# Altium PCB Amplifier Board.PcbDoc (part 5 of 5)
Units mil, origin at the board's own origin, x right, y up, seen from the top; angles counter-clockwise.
Board outline 6000 x 4000 mil, 6 copper layers (Top Layer, GND, VCC, InternalPlane3, InternalPlane4, Bottom Layer); 880 components, 519 nets, 2020 pads, 372 vias.
Unrouted connection lines stored in the file: 585.
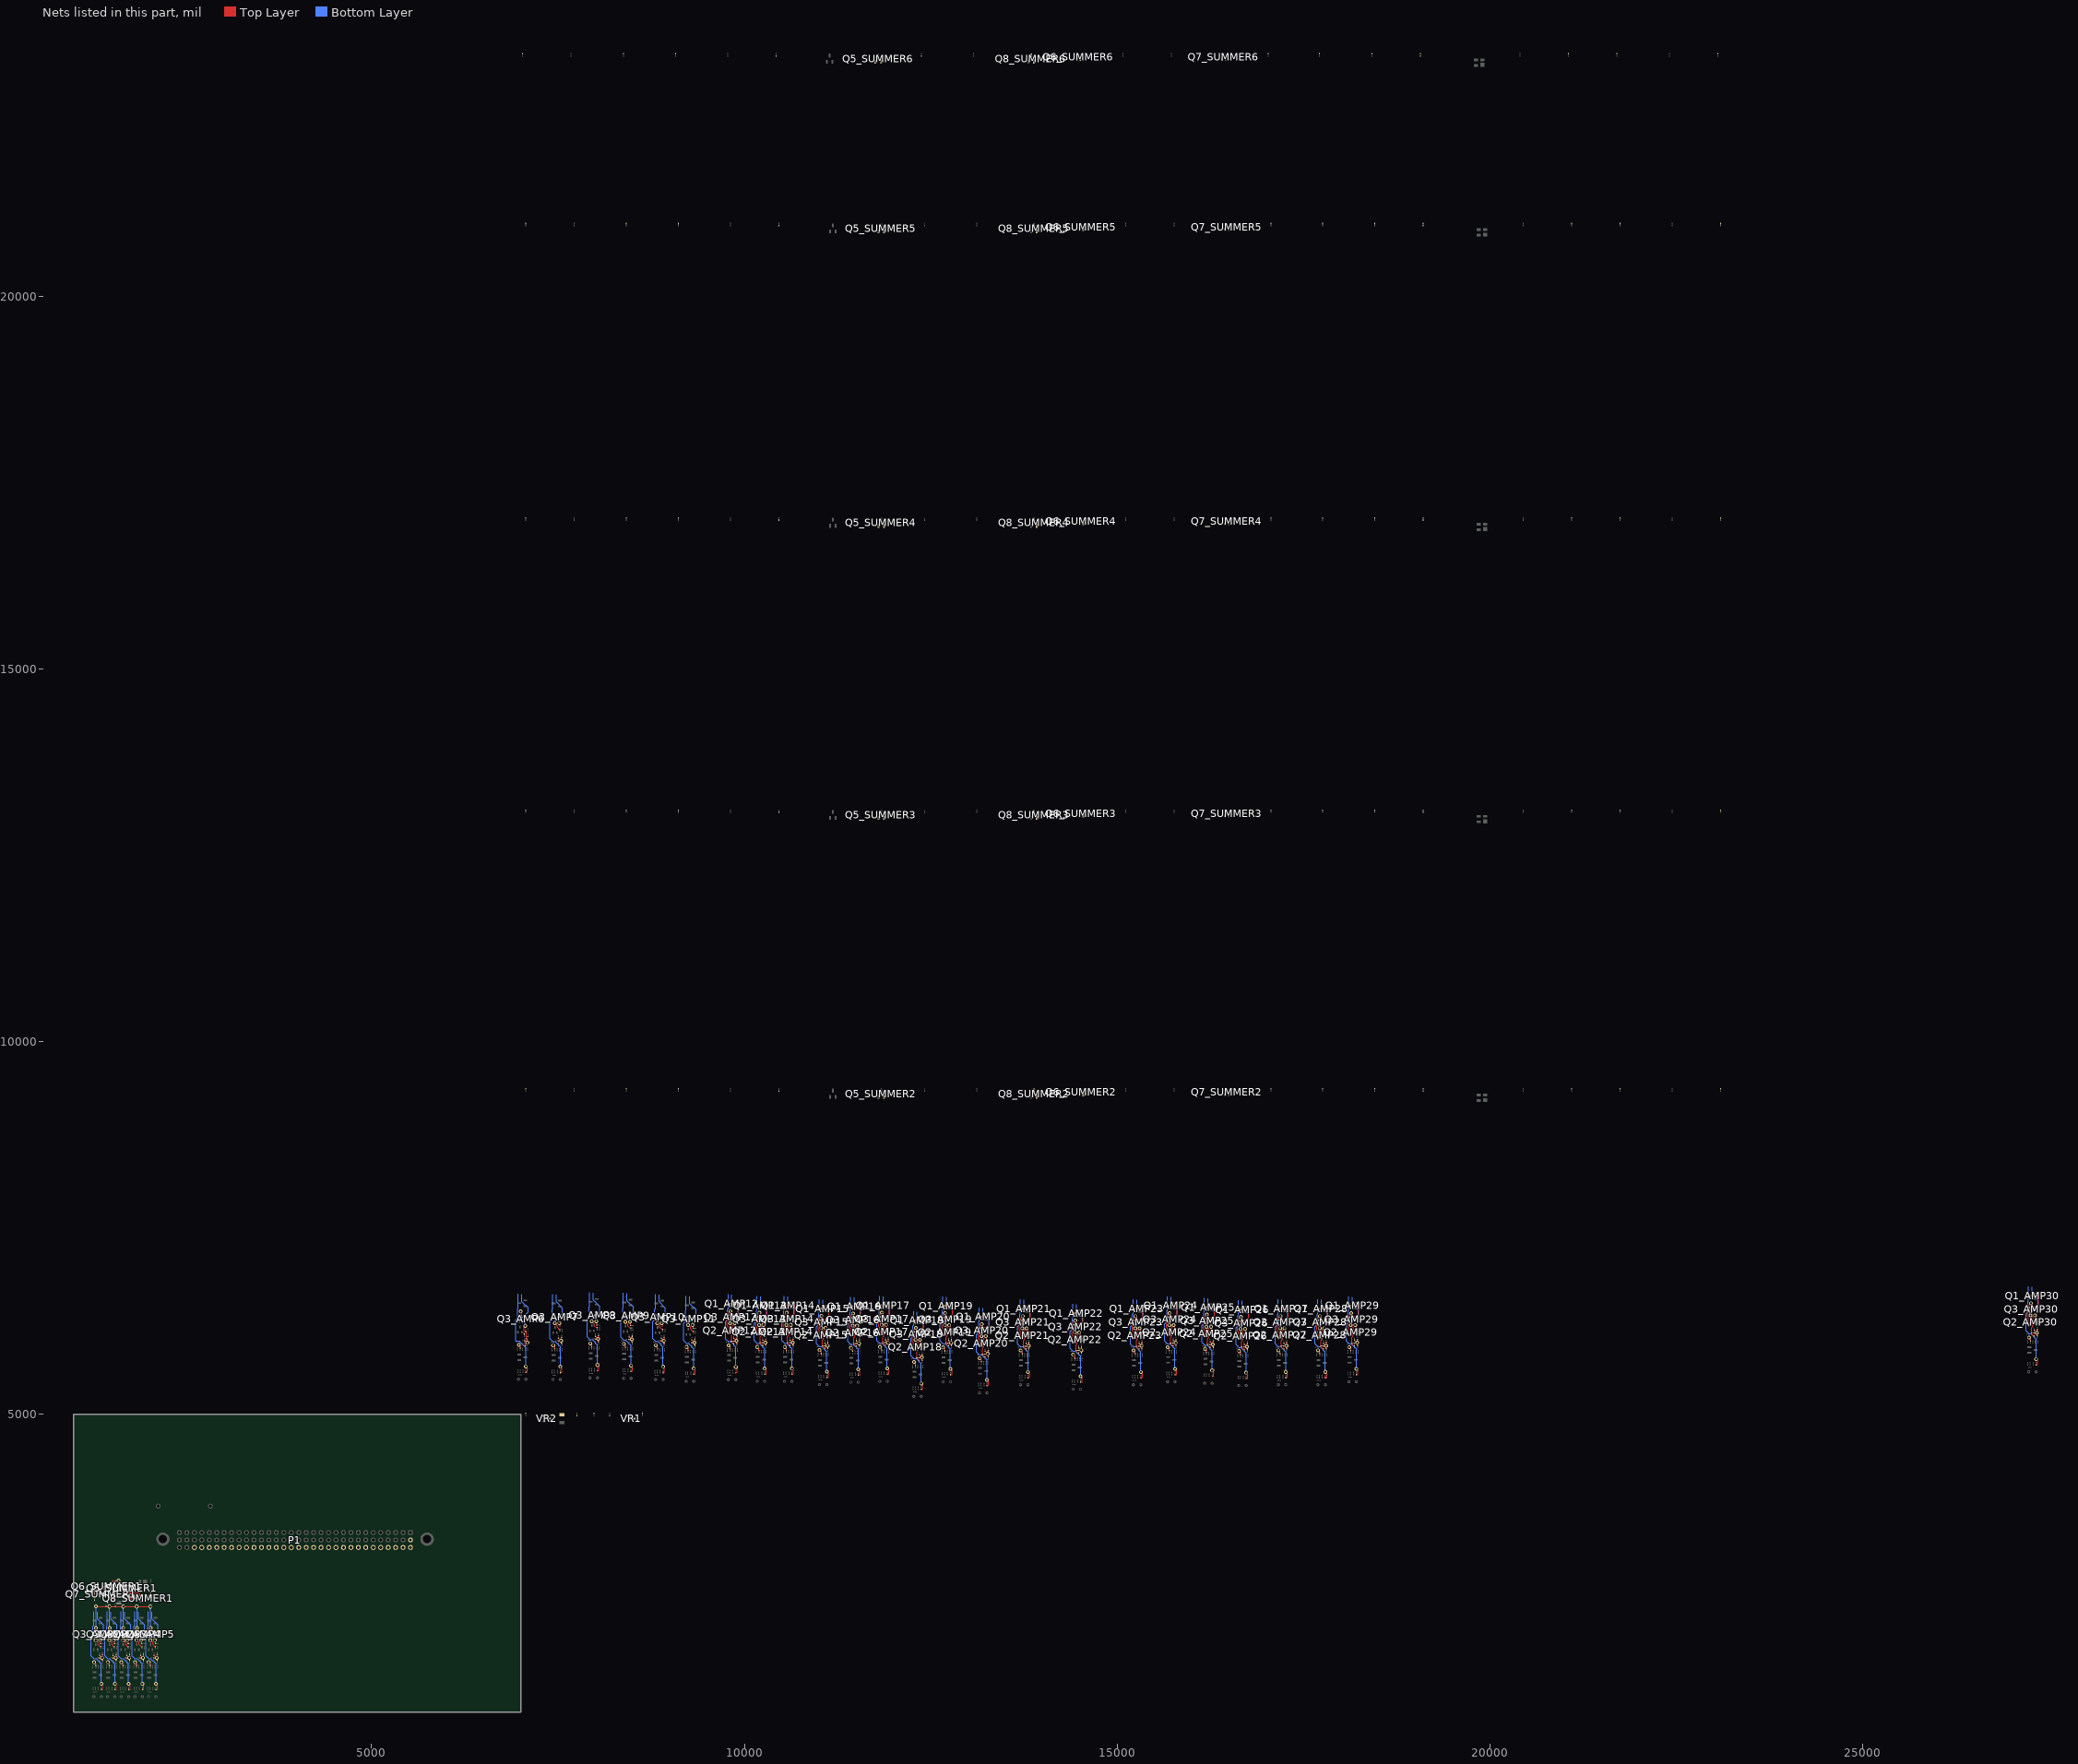
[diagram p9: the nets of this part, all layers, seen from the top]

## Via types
v1: diameter 50, hole 28, Top Layer to Bottom Layer, 371 vias
v2: diameter 50, hole 28, Top Layer to Bottom Layer, tented top, 1 vias

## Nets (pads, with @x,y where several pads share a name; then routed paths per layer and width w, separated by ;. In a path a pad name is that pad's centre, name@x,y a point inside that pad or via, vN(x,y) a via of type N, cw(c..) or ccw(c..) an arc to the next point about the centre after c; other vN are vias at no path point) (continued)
NetQ1_AMP12_3: Q1_AMP12.3 Q2_AMP12.1 Q3_AMP12.1 R2_AMP12.2 R4_AMP12.1 | length 902.3
  Top Layer w7: Q3_AMP12.1@9786.57,6326.59 9786.57,6355.57 v1(9814,6383) v1@9824.57,6372.43 ; Q1_AMP12.3@9793.66,6482 9916,6482 9916,6364 9895,6343 9844,6343 9824,6323 9824,6309 9790.41,6275.41 9786.57,6275.41 9770,6258.84 9770,6194.2 9781.1,6183.1 9781,6183.1 9781,6129 9784,6126 9812,6126 9837.59,6100.41 9837.59,6069.59 9826.22,6058.22 9826.22,5970.78 9851.22,5945.78 R2_AMP12.2@9860,5945.78
NetQ1_AMP13_3: Q1_AMP13.3 Q2_AMP13.1 Q3_AMP13.1 R2_AMP13.2 R4_AMP13.1 | length 902.3
  Top Layer w7: Q3_AMP13.1@10173.57,6304.59 10173.57,6333.57 v1(10201,6361) v1@10211.57,6350.43 ; Q1_AMP13.3@10180.66,6460 10303,6460 10303,6342 10282,6321 10231,6321 10211,6301 10211,6287 10177.41,6253.41 10173.57,6253.41 10157,6236.84 10157,6172.2 10168.1,6161.1 10168,6161.1 10168,6107 10171,6104 10199,6104 10224.59,6078.41 10224.59,6047.59 10213.22,6036.22 10213.22,5948.78 10238.22,5923.78 R2_AMP13.2@10247,5923.78
NetQ1_AMP14_3: Q1_AMP14.3 Q2_AMP14.1 Q3_AMP14.1 R2_AMP14.2 R4_AMP14.1 | length 902.3
  Top Layer w7: Q3_AMP14.1@10539.57,6304.59 10539.57,6333.57 v1(10567,6361) v1@10577.57,6350.43 ; Q1_AMP14.3@10546.66,6460 10669,6460 10669,6342 10648,6321 10597,6321 10577,6301 10577,6287 10543.41,6253.41 10539.57,6253.41 10523,6236.84 10523,6172.2 10534.1,6161.1 10534,6161.1 10534,6107 10537,6104 10565,6104 10590.59,6078.41 10590.59,6047.59 10579.22,6036.22 10579.22,5948.78 10604.22,5923.78 R2_AMP14.2@10613,5923.78
NetQ1_AMP15_3: Q1_AMP15.3 Q2_AMP15.1 Q3_AMP15.1 R2_AMP15.2 R4_AMP15.1 | length 902.3
  Top Layer w7: Q3_AMP15.1@11007.57,6261.59 11007.57,6290.57 v1(11035,6318) v1@11045.57,6307.43 ; Q1_AMP15.3@11014.66,6417 11137,6417 11137,6299 11116,6278 11065,6278 11045,6258 11045,6244 11011.41,6210.41 11007.57,6210.41 10991,6193.84 10991,6129.2 11002.1,6118.1 11002,6118.1 11002,6064 11005,6061 11033,6061 11058.59,6035.41 11058.59,6004.59 11047.22,5993.22 11047.22,5905.78 11072.22,5880.78 R2_AMP15.2@11081,5880.78
NetQ1_AMP16_3: Q1_AMP16.3 Q2_AMP16.1 Q3_AMP16.1 R2_AMP16.2 R4_AMP16.1 | length 902.3
  Top Layer w7: Q3_AMP16.1@11429.57,6293.59 11429.57,6322.57 v1(11457,6350) v1@11467.57,6339.43 ; Q1_AMP16.3@11436.66,6449 11559,6449 11559,6331 11538,6310 11487,6310 11467,6290 11467,6276 11433.41,6242.41 11429.57,6242.41 11413,6225.84 11413,6161.2 11424.1,6150.1 11424,6150.1 11424,6096 11427,6093 11455,6093 11480.59,6067.41 11480.59,6036.59 11469.22,6025.22 11469.22,5937.78 11494.22,5912.78 R2_AMP16.2@11503,5912.78
NetQ1_AMP17_3: Q1_AMP17.3 Q2_AMP17.1 Q3_AMP17.1 R2_AMP17.2 R4_AMP17.1 | length 902.3
  Top Layer w7: Q3_AMP17.1@11817.57,6305.59 11817.57,6334.57 v1(11845,6362) v1@11855.57,6351.43 ; Q1_AMP17.3@11824.66,6461 11947,6461 11947,6343 11926,6322 11875,6322 11855,6302 11855,6288 11821.41,6254.41 11817.57,6254.41 11801,6237.84 11801,6173.2 11812.1,6162.1 11812,6162.1 11812,6108 11815,6105 11843,6105 11868.59,6079.41 11868.59,6048.59 11857.22,6037.22 11857.22,5949.78 11882.22,5924.78 R2_AMP17.2@11891,5924.78
NetQ1_AMP18_3: Q1_AMP18.3 Q2_AMP18.1 Q3_AMP18.1 R2_AMP18.2 R4_AMP18.1 | length 902.3
  Top Layer w7: Q3_AMP18.1@12273.57,6103.59 12273.57,6132.57 v1(12301,6160) v1@12311.57,6149.43 ; Q1_AMP18.3@12280.66,6259 12403,6259 12403,6141 12382,6120 12331,6120 12311,6100 12311,6086 12277.41,6052.41 12273.57,6052.41 12257,6035.84 12257,5971.2 12268.1,5960.1 12268,5960.1 12268,5906 12271,5903 12299,5903 12324.59,5877.41 12324.59,5846.59 12313.22,5835.22 12313.22,5747.78 12338.22,5722.78 R2_AMP18.2@12347,5722.78
NetQ1_AMP19_3: Q1_AMP19.3 Q2_AMP19.1 Q3_AMP19.1 R2_AMP19.2 R4_AMP19.1 | length 902.3
  Top Layer w7: Q3_AMP19.1@12665.57,6299.59 12665.57,6328.57 v1(12693,6356) v1@12703.57,6345.43 ; Q1_AMP19.3@12672.66,6455 12795,6455 12795,6337 12774,6316 12723,6316 12703,6296 12703,6282 12669.41,6248.41 12665.57,6248.41 12649,6231.84 12649,6167.2 12660.1,6156.1 12660,6156.1 12660,6102 12663,6099 12691,6099 12716.59,6073.41 12716.59,6042.59 12705.22,6031.22 12705.22,5943.78 12730.22,5918.78 R2_AMP19.2@12739,5918.78
NetQ1_AMP20_3: Q1_AMP20.3 Q2_AMP20.1 Q3_AMP20.1 R2_AMP20.2 R4_AMP20.1 | length 902.3
  Top Layer w7: Q3_AMP20.1@13155.57,6152.59 13155.57,6181.57 v1(13183,6209) v1@13193.57,6198.43 ; Q1_AMP20.3@13162.66,6308 13285,6308 13285,6190 13264,6169 13213,6169 13193,6149 13193,6135 13159.41,6101.41 13155.57,6101.41 13139,6084.84 13139,6020.2 13150.1,6009.1 13150,6009.1 13150,5955 13153,5952 13181,5952 13206.59,5926.41 13206.59,5895.59 13195.22,5884.22 13195.22,5796.78 13220.22,5771.78 R2_AMP20.2@13229,5771.78
NetQ1_AMP21_3: Q1_AMP21.3 Q2_AMP21.1 Q3_AMP21.1 R2_AMP21.2 R4_AMP21.1 | length 902.3
  Top Layer w7: Q3_AMP21.1@13705.57,6258.59 13705.57,6287.57 v1(13733,6315) v1@13743.57,6304.43 ; Q1_AMP21.3@13712.66,6414 13835,6414 13835,6296 13814,6275 13763,6275 13743,6255 13743,6241 13709.41,6207.41 13705.57,6207.41 13689,6190.84 13689,6126.2 13700.1,6115.1 13700,6115.1 13700,6061 13703,6058 13731,6058 13756.59,6032.41 13756.59,6001.59 13745.22,5990.22 13745.22,5902.78 13770.22,5877.78 R2_AMP21.2@13779,5877.78
NetQ1_AMP22_3: Q1_AMP22.3 Q2_AMP22.1 Q3_AMP22.1 R2_AMP22.2 R4_AMP22.1 | length 902.3
  Top Layer w7: Q3_AMP22.1@14410.57,6200.59 14410.57,6229.57 v1(14438,6257) v1@14448.57,6246.43 ; Q1_AMP22.3@14417.66,6356 14540,6356 14540,6238 14519,6217 14468,6217 14448,6197 14448,6183 14414.41,6149.41 14410.57,6149.41 14394,6132.84 14394,6068.2 14405.1,6057.1 14405,6057.1 14405,6003 14408,6000 14436,6000 14461.59,5974.41 14461.59,5943.59 14450.22,5932.22 14450.22,5844.78 14475.22,5819.78 R2_AMP22.2@14484,5819.78
NetQ1_AMP23_3: Q1_AMP23.3 Q2_AMP23.1 Q3_AMP23.1 R2_AMP23.2 R4_AMP23.1 | length 902.3
  Top Layer w7: Q3_AMP23.1@15219.57,6258.59 15219.57,6287.57 v1(15247,6315) v1@15257.57,6304.43 ; Q1_AMP23.3@15226.66,6414 15349,6414 15349,6296 15328,6275 15277,6275 15257,6255 15257,6241 15223.41,6207.41 15219.57,6207.41 15203,6190.84 15203,6126.2 15214.1,6115.1 15214,6115.1 15214,6061 15217,6058 15245,6058 15270.59,6032.41 15270.59,6001.59 15259.22,5990.22 15259.22,5902.78 15284.22,5877.78 R2_AMP23.2@15293,5877.78
NetQ1_AMP24_3: Q1_AMP24.3 Q2_AMP24.1 Q3_AMP24.1 R2_AMP24.2 R4_AMP24.1 | length 902.3
  Top Layer w7: Q3_AMP24.1@15677.57,6300.59 15677.57,6329.57 v1(15705,6357) v1@15715.57,6346.43 ; Q1_AMP24.3@15684.66,6456 15807,6456 15807,6338 15786,6317 15735,6317 15715,6297 15715,6283 15681.41,6249.41 15677.57,6249.41 15661,6232.84 15661,6168.2 15672.1,6157.1 15672,6157.1 15672,6103 15675,6100 15703,6100 15728.59,6074.41 15728.59,6043.59 15717.22,6032.22 15717.22,5944.78 15742.22,5919.78 R2_AMP24.2@15751,5919.78
NetQ1_AMP25_3: Q1_AMP25.3 Q2_AMP25.1 Q3_AMP25.1 R2_AMP25.2 R4_AMP25.1 | length 902.3
  Top Layer w7: Q3_AMP25.1@16176.57,6279.59 16176.57,6308.57 v1(16204,6336) v1@16214.57,6325.43 ; Q1_AMP25.3@16183.66,6435 16306,6435 16306,6317 16285,6296 16234,6296 16214,6276 16214,6262 16180.41,6228.41 16176.57,6228.41 16160,6211.84 16160,6147.2 16171.1,6136.1 16171,6136.1 16171,6082 16174,6079 16202,6079 16227.59,6053.41 16227.59,6022.59 16216.22,6011.22 16216.22,5923.78 16241.22,5898.78 R2_AMP25.2@16250,5898.78
NetQ1_AMP26_3: Q1_AMP26.3 Q2_AMP26.1 Q3_AMP26.1 R2_AMP26.2 R4_AMP26.1 | length 902.3
  Top Layer w7: Q3_AMP26.1@16633.57,6248.59 16633.57,6277.57 v1(16661,6305) v1@16671.57,6294.43 ; Q1_AMP26.3@16640.66,6404 16763,6404 16763,6286 16742,6265 16691,6265 16671,6245 16671,6231 16637.41,6197.41 16633.57,6197.41 16617,6180.84 16617,6116.2 16628.1,6105.1 16628,6105.1 16628,6051 16631,6048 16659,6048 16684.59,6022.41 16684.59,5991.59 16673.22,5980.22 16673.22,5892.78 16698.22,5867.78 R2_AMP26.2@16707,5867.78
NetQ1_AMP27_3: Q1_AMP27.3 Q2_AMP27.1 Q3_AMP27.1 R2_AMP27.2 R4_AMP27.1 | length 902.3
  Top Layer w7: Q3_AMP27.1@17163.57,6259.59 17163.57,6288.57 v1(17191,6316) v1@17201.57,6305.43 ; Q1_AMP27.3@17170.66,6415 17293,6415 17293,6297 17272,6276 17221,6276 17201,6256 17201,6242 17167.41,6208.41 17163.57,6208.41 17147,6191.84 17147,6127.2 17158.1,6116.1 17158,6116.1 17158,6062 17161,6059 17189,6059 17214.59,6033.41 17214.59,6002.59 17203.22,5991.22 17203.22,5903.78 17228.22,5878.78 R2_AMP27.2@17237,5878.78
NetQ1_AMP28_3: Q1_AMP28.3 Q2_AMP28.1 Q3_AMP28.1 R2_AMP28.2 R4_AMP28.1 | length 902.3
  Top Layer w7: Q3_AMP28.1@17694.57,6259.59 17694.57,6288.57 v1(17722,6316) v1@17732.57,6305.43 ; Q1_AMP28.3@17701.66,6415 17824,6415 17824,6297 17803,6276 17752,6276 17732,6256 17732,6242 17698.41,6208.41 17694.57,6208.41 17678,6191.84 17678,6127.2 17689.1,6116.1 17689,6116.1 17689,6062 17692,6059 17720,6059 17745.59,6033.41 17745.59,6002.59 17734.22,5991.22 17734.22,5903.78 17759.22,5878.78 R2_AMP28.2@17768,5878.78
NetQ1_AMP29_3: Q1_AMP29.3 Q2_AMP29.1 Q3_AMP29.1 R2_AMP29.2 R4_AMP29.1 | length 902.3
  Top Layer w7: Q3_AMP29.1@18111.57,6300.59 18111.57,6329.57 v1(18139,6357) v1@18149.57,6346.43 ; Q1_AMP29.3@18118.66,6456 18241,6456 18241,6338 18220,6317 18169,6317 18149,6297 18149,6283 18115.41,6249.41 18111.57,6249.41 18095,6232.84 18095,6168.2 18106.1,6157.1 18106,6157.1 18106,6103 18109,6100 18137,6100 18162.59,6074.41 18162.59,6043.59 18151.22,6032.22 18151.22,5944.78 18176.22,5919.78 R2_AMP29.2@18185,5919.78
NetQ1_AMP30_3: Q1_AMP30.3 Q2_AMP30.1 Q3_AMP30.1 R2_AMP30.2 R4_AMP30.1 | length 902.3
  Top Layer w7: Q3_AMP30.1@27229.57,6432.59 27229.57,6461.57 v1(27257,6489) v1@27267.57,6478.43 ; Q1_AMP30.3@27236.66,6588 27359,6588 27359,6470 27338,6449 27287,6449 27267,6429 27267,6415 27233.41,6381.41 27229.57,6381.41 27213,6364.84 27213,6300.2 27224.1,6289.1 27224,6289.1 27224,6235 27227,6232 27255,6232 27280.59,6206.41 27280.59,6175.59 27269.22,6164.22 27269.22,6076.78 27294.22,6051.78 R2_AMP30.2@27303,6051.78
NetQ5_SUMMER1_1: Q5_SUMMER1.1 Q8_SUMMER1.2 R17_SUMMER1.2 | length 295.5
  Top Layer w7: Q5_SUMMER1.1@1695.34,2629.6 1695.34,2618.56 1706.9,2607 1866.74,2607 Q8_SUMMER1.2@1906.34,2567.4 ; Q5_SUMMER1.1@1697.94,2627 R17_SUMMER1.2@1750.22,2627
NetQ5_SUMMER1_2: Q5_SUMMER1.2 R14_SUMMER1.2 | length 52.5
  Top Layer w7: Q5_SUMMER1.2@1697.74,2702 R14_SUMMER1.2@1750.22,2702
NetQ5_SUMMER2_1: Q5_SUMMER2.1 Q8_SUMMER2.2 R17_SUMMER2.2
NetQ5_SUMMER2_2: Q5_SUMMER2.2 R14_SUMMER2.2
NetQ5_SUMMER3_1: Q5_SUMMER3.1 Q8_SUMMER3.2 R17_SUMMER3.2
NetQ5_SUMMER3_2: Q5_SUMMER3.2 R14_SUMMER3.2
NetQ5_SUMMER4_1: Q5_SUMMER4.1 Q8_SUMMER4.2 R17_SUMMER4.2
NetQ5_SUMMER4_2: Q5_SUMMER4.2 R14_SUMMER4.2
NetQ5_SUMMER5_1: Q5_SUMMER5.1 Q8_SUMMER5.2 R17_SUMMER5.2
NetQ5_SUMMER5_2: Q5_SUMMER5.2 R14_SUMMER5.2
NetQ5_SUMMER6_1: Q5_SUMMER6.1 Q8_SUMMER6.2 R17_SUMMER6.2
NetQ5_SUMMER6_2: Q5_SUMMER6.2 R14_SUMMER6.2
NetQ6_SUMMER1_2: Q6_SUMMER1.2 Q7_SUMMER1.1 R15_SUMMER1.1 | length 134.4
  Top Layer w7: R15_SUMMER1.1@1354.56,2655 1410.43,2655 ; 1410.43,2610.59 1410.43,2689.13
NetQ6_SUMMER2_2: Q6_SUMMER2.2 Q7_SUMMER2.1 R15_SUMMER2.1
NetQ6_SUMMER3_2: Q6_SUMMER3.2 Q7_SUMMER3.1 R15_SUMMER3.1
NetQ6_SUMMER4_2: Q6_SUMMER4.2 Q7_SUMMER4.1 R15_SUMMER4.1
NetQ6_SUMMER5_2: Q6_SUMMER5.2 Q7_SUMMER5.1 R15_SUMMER5.1
NetQ6_SUMMER6_2: Q6_SUMMER6.2 Q7_SUMMER6.1 R15_SUMMER6.1
NetR18_AMP1_1: R18_AMP1.1 | length 1176.1
  Top Layer w7: R18_AMP1.1@1374,1304 1376.56,1306.56 1394,1306.56 1394,1351.56 1374,1371.56 v1(1374,1381.56)
  Bottom Layer w7: 1272,2351 1272,2163 1264,2155 1264,2094 1281,2077 1281,2031 1237,1987 1237,1757 1274,1720 1303,1720 1374,1649 v1(1374,1381.56)
NetR18_AMP2_1: R18_AMP2.1 | length 1176.1
  Top Layer w7: R18_AMP2.1@1557,1304 1559.56,1306.56 1577,1306.56 1577,1351.56 1557,1371.56 v1(1557,1381.56)
  Bottom Layer w7: 1455,2351 1455,2163 1447,2155 1447,2094 1464,2077 1464,2031 1420,1987 1420,1757 1457,1720 1486,1720 1557,1649 v1(1557,1381.56)
NetR18_AMP3_1: R18_AMP3.1 | length 1176.1
  Top Layer w7: R18_AMP3.1@1740,1304 1742.56,1306.56 1760,1306.56 1760,1351.56 1740,1371.56 v1(1740,1381.56)
  Bottom Layer w7: 1638,2351 1638,2163 1630,2155 1630,2094 1647,2077 1647,2031 1603,1987 1603,1757 1640,1720 1669,1720 1740,1649 v1(1740,1381.56)
NetR18_AMP4_1: R18_AMP4.1 | length 1176.1
  Top Layer w7: R18_AMP4.1@1924,1304 1926.56,1306.56 1944,1306.56 1944,1351.56 1924,1371.56 v1(1924,1381.56)
  Bottom Layer w7: 1822,2351 1822,2163 1814,2155 1814,2094 1831,2077 1831,2031 1787,1987 1787,1757 1824,1720 1853,1720 1924,1649 v1(1924,1381.56)
NetR18_AMP5_1: R18_AMP5.1 | length 1176.1
  Top Layer w7: R18_AMP5.1@2107,1304 2109.56,1306.56 2127,1306.56 2127,1351.56 2107,1371.56 v1(2107,1381.56)
  Bottom Layer w7: 2005,2351 2005,2163 1997,2155 1997,2094 2014,2077 2014,2031 1970,1987 1970,1757 2007,1720 2036,1720 2107,1649 v1(2107,1381.56)
NetR18_AMP6_1: R18_AMP6.1 | length 1177.2
  Top Layer w7: R18_AMP6.1@7070,5564 7072.56,5566.56 7090,5566.56 7090,5611.56 7070,5631.56 v1(7070,5641.56)
  Bottom Layer w7: 6968,6611 6968,6423 6960,6415 6960,6354 6959.88,6354.12 6959.88,6290.88 6933,6264 6933,5980 6987.56,5980 6987.56,5971.44 7070,5889 v1(7070,5641.56)
NetR18_AMP7_1: R18_AMP7.1 | length 1176.1
  Top Layer w7: R18_AMP7.1@7532,5559 7534.56,5561.56 7552,5561.56 7552,5606.56 7532,5626.56 v1(7532,5636.56)
  Bottom Layer w7: 7430,6606 7430,6418 7422,6410 7422,6349 7439,6332 7439,6286 7395,6242 7395,6012 7432,5975 7461,5975 7532,5904 v1(7532,5636.56)
NetR18_AMP8_1: R18_AMP8.1 | length 1176.1
  Top Layer w7: R18_AMP8.1@8029,5583 8031.56,5585.56 8049,5585.56 8049,5630.56 8029,5650.56 v1(8029,5660.56)
  Bottom Layer w7: 7927,6630 7927,6442 7919,6434 7919,6373 7936,6356 7936,6310 7892,6266 7892,6036 7929,5999 7958,5999 8029,5928 v1(8029,5660.56)
NetR18_AMP9_1: R18_AMP9.1 | length 1176.1
  Top Layer w7: R18_AMP9.1@8480,5576 8482.56,5578.56 8500,5578.56 8500,5623.56 8480,5643.56 v1(8480,5653.56)
  Bottom Layer w7: 8378,6623 8378,6435 8370,6427 8370,6366 8387,6349 8387,6303 8343,6259 8343,6029 8380,5992 8409,5992 8480,5921 v1(8480,5653.56)
NetR18_AMP10_1: R18_AMP10.1 | length 1176.1
  Top Layer w7: R18_AMP10.1@8909,5559 8911.56,5561.56 8929,5561.56 8929,5606.56 8909,5626.56 v1(8909,5636.56)
  Bottom Layer w7: 8807,6606 8807,6418 8799,6410 8799,6349 8816,6332 8816,6286 8772,6242 8772,6012 8809,5975 8838,5975 8909,5904 v1(8909,5636.56)
NetR18_AMP11_1: R18_AMP11.1 | length 1176.1
  Top Layer w7: R18_AMP11.1@9321,5535 9323.56,5537.56 9341,5537.56 9341,5582.56 9321,5602.56 v1(9321,5612.56)
  Bottom Layer w7: 9219,6582 9219,6394 9211,6386 9211,6325 9228,6308 9228,6262 9184,6218 9184,5988 9221,5951 9250,5951 9321,5880 v1(9321,5612.56)
NetR18_AMP12_1: R18_AMP12.1 | length 1176.1
  Top Layer w7: R18_AMP12.1@9885,5557 9887.56,5559.56 9905,5559.56 9905,5604.56 9885,5624.56 v1(9885,5634.56)
  Bottom Layer w7: 9783,6604 9783,6416 9775,6408 9775,6347 9792,6330 9792,6284 9748,6240 9748,6010 9785,5973 9814,5973 9885,5902 v1(9885,5634.56)
NetR18_AMP13_1: R18_AMP13.1 | length 1176.1
  Top Layer w7: R18_AMP13.1@10272,5535 10274.56,5537.56 10292,5537.56 10292,5582.56 10272,5602.56 v1(10272,5612.56)
  Bottom Layer w7: 10170,6582 10170,6394 10162,6386 10162,6325 10179,6308 10179,6262 10135,6218 10135,5988 10172,5951 10201,5951 10272,5880 v1(10272,5612.56)
NetR18_AMP14_1: R18_AMP14.1 | length 1176.1
  Top Layer w7: R18_AMP14.1@10638,5535 10640.56,5537.56 10658,5537.56 10658,5582.56 10638,5602.56 v1(10638,5612.56)
  Bottom Layer w7: 10536,6582 10536,6394 10528,6386 10528,6325 10545,6308 10545,6262 10501,6218 10501,5988 10538,5951 10567,5951 10638,5880 v1(10638,5612.56)
NetR18_AMP15_1: R18_AMP15.1 | length 1176.1
  Top Layer w7: R18_AMP15.1@11106,5492 11108.56,5494.56 11126,5494.56 11126,5539.56 11106,5559.56 v1(11106,5569.56)
  Bottom Layer w7: 11004,6539 11004,6351 10996,6343 10996,6282 11013,6265 11013,6219 10969,6175 10969,5945 11006,5908 11035,5908 11106,5837 v1(11106,5569.56)
NetR18_AMP16_1: R18_AMP16.1 | length 1176.1
  Top Layer w7: R18_AMP16.1@11528,5524 11530.56,5526.56 11548,5526.56 11548,5571.56 11528,5591.56 v1(11528,5601.56)
  Bottom Layer w7: 11426,6571 11426,6383 11418,6375 11418,6314 11435,6297 11435,6251 11391,6207 11391,5977 11428,5940 11457,5940 11528,5869 v1(11528,5601.56)
NetR18_AMP17_1: R18_AMP17.1 | length 1176.1
  Top Layer w7: R18_AMP17.1@11916,5536 11918.56,5538.56 11936,5538.56 11936,5583.56 11916,5603.56 v1(11916,5613.56)
  Bottom Layer w7: 11814,6583 11814,6395 11806,6387 11806,6326 11823,6309 11823,6263 11779,6219 11779,5989 11816,5952 11845,5952 11916,5881 v1(11916,5613.56)
NetR18_AMP18_1: R18_AMP18.1 | length 1176.1
  Top Layer w7: R18_AMP18.1@12372,5334 12374.56,5336.56 12392,5336.56 12392,5381.56 12372,5401.56 v1(12372,5411.56)
  Bottom Layer w7: 12270,6381 12270,6193 12262,6185 12262,6124 12279,6107 12279,6061 12235,6017 12235,5787 12272,5750 12301,5750 12372,5679 v1(12372,5411.56)
NetR18_AMP19_1: R18_AMP19.1 | length 1176.1
  Top Layer w7: R18_AMP19.1@12764,5530 12766.56,5532.56 12784,5532.56 12784,5577.56 12764,5597.56 v1(12764,5607.56)
  Bottom Layer w7: 12662,6577 12662,6389 12654,6381 12654,6320 12671,6303 12671,6257 12627,6213 12627,5983 12664,5946 12693,5946 12764,5875 v1(12764,5607.56)
NetR18_AMP20_1: R18_AMP20.1 | length 1176.1
  Top Layer w7: R18_AMP20.1@13254,5383 13256.56,5385.56 13274,5385.56 13274,5430.56 13254,5450.56 v1(13254,5460.56)
  Bottom Layer w7: 13152,6430 13152,6242 13144,6234 13144,6173 13161,6156 13161,6110 13117,6066 13117,5836 13154,5799 13183,5799 13254,5728 v1(13254,5460.56)
NetR18_AMP21_1: R18_AMP21.1 | length 1176.1
  Top Layer w7: R18_AMP21.1@13804,5489 13806.56,5491.56 13824,5491.56 13824,5536.56 13804,5556.56 v1(13804,5566.56)
  Bottom Layer w7: 13702,6536 13702,6348 13694,6340 13694,6279 13711,6262 13711,6216 13667,6172 13667,5942 13704,5905 13733,5905 13804,5834 v1(13804,5566.56)
NetR18_AMP22_1: R18_AMP22.1 | length 1176.1
  Top Layer w7: R18_AMP22.1@14509,5431 14511.56,5433.56 14529,5433.56 14529,5478.56 14509,5498.56 v1(14509,5508.56)
  Bottom Layer w7: 14407,6478 14407,6290 14399,6282 14399,6221 14416,6204 14416,6158 14372,6114 14372,5884 14409,5847 14438,5847 14509,5776 v1(14509,5508.56)
NetR18_AMP23_1: R18_AMP23.1 | length 1176.1
  Top Layer w7: R18_AMP23.1@15318,5489 15320.56,5491.56 15338,5491.56 15338,5536.56 15318,5556.56 v1(15318,5566.56)
  Bottom Layer w7: 15216,6536 15216,6348 15208,6340 15208,6279 15225,6262 15225,6216 15181,6172 15181,5942 15218,5905 15247,5905 15318,5834 v1(15318,5566.56)
NetR18_AMP24_1: R18_AMP24.1 | length 1176.1
  Top Layer w7: R18_AMP24.1@15776,5531 15778.56,5533.56 15796,5533.56 15796,5578.56 15776,5598.56 v1(15776,5608.56)
  Bottom Layer w7: 15674,6578 15674,6390 15666,6382 15666,6321 15683,6304 15683,6258 15639,6214 15639,5984 15676,5947 15705,5947 15776,5876 v1(15776,5608.56)
NetR18_AMP25_1: R18_AMP25.1 | length 1176.1
  Top Layer w7: R18_AMP25.1@16275,5510 16277.56,5512.56 16295,5512.56 16295,5557.56 16275,5577.56 v1(16275,5587.56)
  Bottom Layer w7: 16173,6557 16173,6369 16165,6361 16165,6300 16182,6283 16182,6237 16138,6193 16138,5963 16175,5926 16204,5926 16275,5855 v1(16275,5587.56)
NetR18_AMP26_1: R18_AMP26.1 | length 1176.1
  Top Layer w7: R18_AMP26.1@16732,5479 16734.56,5481.56 16752,5481.56 16752,5526.56 16732,5546.56 v1(16732,5556.56)
  Bottom Layer w7: 16630,6526 16630,6338 16622,6330 16622,6269 16639,6252 16639,6206 16595,6162 16595,5932 16632,5895 16661,5895 16732,5824 v1(16732,5556.56)
NetR18_AMP27_1: R18_AMP27.1 | length 1176.1
  Top Layer w7: R18_AMP27.1@17262,5490 17264.56,5492.56 17282,5492.56 17282,5537.56 17262,5557.56 v1(17262,5567.56)
  Bottom Layer w7: 17160,6537 17160,6349 17152,6341 17152,6280 17169,6263 17169,6217 17125,6173 17125,5943 17162,5906 17191,5906 17262,5835 v1(17262,5567.56)
NetR18_AMP28_1: R18_AMP28.1 | length 1176.1
  Top Layer w7: R18_AMP28.1@17793,5490 17795.56,5492.56 17813,5492.56 17813,5537.56 17793,5557.56 v1(17793,5567.56)
  Bottom Layer w7: 17691,6537 17691,6349 17683,6341 17683,6280 17700,6263 17700,6217 17656,6173 17656,5943 17693,5906 17722,5906 17793,5835 v1(17793,5567.56)
NetR18_AMP29_1: R18_AMP29.1 | length 1176.1
  Top Layer w7: R18_AMP29.1@18210,5531 18212.56,5533.56 18230,5533.56 18230,5578.56 18210,5598.56 v1(18210,5608.56)
  Bottom Layer w7: 18108,6578 18108,6390 18100,6382 18100,6321 18117,6304 18117,6258 18073,6214 18073,5984 18110,5947 18139,5947 18210,5876 v1(18210,5608.56)
NetR18_AMP30_1: R18_AMP30.1 | length 1176.1
  Top Layer w7: R18_AMP30.1@27328,5663 27330.56,5665.56 27348,5665.56 27348,5710.56 27328,5730.56 v1(27328,5740.56)
  Bottom Layer w7: 27226,6710 27226,6522 27218,6514 27218,6453 27235,6436 27235,6390 27191,6346 27191,6116 27228,6079 27257,6079 27328,6008 v1(27328,5740.56)
NetR21_2: R21.2 R22.1 VR1.1
NetR23_2: R23.2 R24.1 VR2.1
NetR25_2: R25.2 RBi_SUMMER1.1 RBi_SUMMER2.1 RBi_SUMMER3.1 RBi_SUMMER4.1 RBi_SUMMER5.1 RBi_SUMMER6.1 VR1.3 | length 65.9
  Top Layer w7: v1(1484,2553) 1517,2520 RBi_SUMMER1.1@1536.22,2520
NetR26_2: R26.2 RBi_AMP1.1 RBi_AMP2.1 RBi_AMP3.1 RBi_AMP4.1 RBi_AMP5.1 RBi_AMP6.1 RBi_AMP7.1 RBi_AMP8.1 RBi_AMP9.1 RBi_AMP10.1 RBi_AMP11.1 RBi_AMP12.1 RBi_AMP13.1 RBi_AMP14.1 RBi_AMP15.1 RBi_AMP16.1 RBi_AMP17.1 RBi_AMP18.1 RBi_AMP19.1 RBi_AMP20.1 RBi_AMP21.1 RBi_AMP22.1 RBi_AMP23.1 RBi_AMP24.1 RBi_AMP25.1 RBi_AMP26.1 RBi_AMP27.1 RBi_AMP28.1 RBi_AMP29.1 RBi_AMP30.1 VR2.3 | length 2007.6
  Top Layer w7: v1@1287,1671 v1(1277,1671) 1298,1650 1299,1650 RBi_AMP1.1@1299,1623.78 ; v1@1470,1671 v1(1460,1671) 1481,1650 1482,1650 RBi_AMP2.1@1482,1623.78 ; v1@1653,1671 v1(1643,1671) 1664,1650 1665,1650 RBi_AMP3.1@1665,1623.78 ; v1@1837,1671 v1(1827,1671) 1848,1650 1849,1650 RBi_AMP4.1@1849,1623.78 ; v1@2020,1671 v1(2010,1671) 2031,1650 2032,1650 RBi_AMP5.1@2032,1623.78 ; v1@6983,5931 v1(6973,5931) 6994,5910 6995,5910 RBi_AMP6.1@6995,5883.78 ; v1@7445,5926 v1(7435,5926) 7456,5905 7457,5905 RBi_AMP7.1@7457,5878.78 ; v1@7942,5950 v1(7932,5950) 7953,5929 7954,5929 RBi_AMP8.1@7954,5902.78 ; v1@8393,5943 v1(8383,5943) 8404,5922 8405,5922 RBi_AMP9.1@8405,5895.78 ; v1@8822,5926 v1(8812,5926) 8833,5905 8834,5905 RBi_AMP10.1@8834,5878.78 ; v1@9234,5902 v1(9224,5902) 9245,5881 9246,5881 RBi_AMP11.1@9246,5854.78 ; v1@9798,5924 v1(9788,5924) 9809,5903 9810,5903 RBi_AMP12.1@9810,5876.78 ; v1@10185,5902 v1(10175,5902) 10196,5881 10197,5881 RBi_AMP13.1@10197,5854.78 ; v1@10551,5902 v1(10541,5902) 10562,5881 10563,5881 RBi_AMP14.1@10563,5854.78 ; v1@11019,5859 v1(11009,5859) 11030,5838 11031,5838 RBi_AMP15.1@11031,5811.78 ; v1@11441,5891 v1(11431,5891) 11452,5870 11453,5870 RBi_AMP16.1@11453,5843.78 ; v1@11829,5903 v1(11819,5903) 11840,5882 11841,5882 RBi_AMP17.1@11841,5855.78 ; v1@12285,5701 v1(12275,5701) 12296,5680 12297,5680 RBi_AMP18.1@12297,5653.78 ; v1@12677,5897 v1(12667,5897) 12688,5876 12689,5876 RBi_AMP19.1@12689,5849.78 ; v1@13167,5750 v1(13157,5750) 13178,5729 13179,5729 RBi_AMP20.1@13179,5702.78 ; v1@13717,5856 v1(13707,5856) 13728,5835 13729,5835 RBi_AMP21.1@13729,5808.78 ; v1@14422,5798 v1(14412,5798) 14433,5777 14434,5777 RBi_AMP22.1@14434,5750.78 ; v1@15231,5856 v1(15221,5856) 15242,5835 15243,5835 RBi_AMP23.1@15243,5808.78 ; v1@15689,5898 v1(15679,5898) 15700,5877 15701,5877 RBi_AMP24.1@15701,5850.78 ; v1@16188,5877 v1(16178,5877) 16199,5856 16200,5856 RBi_AMP25.1@16200,5829.78 ; v1@16645,5846 v1(16635,5846) 16656,5825 16657,5825 RBi_AMP26.1@16657,5798.78 ; v1@17175,5857 v1(17165,5857) 17186,5836 17187,5836 RBi_AMP27.1@17187,5809.78 ; v1@17706,5857 v1(17696,5857) 17717,5836 17718,5836 RBi_AMP28.1@17718,5809.78 ; v1@18123,5898 v1(18113,5898) 18134,5877 18135,5877 RBi_AMP29.1@18135,5850.78 ; v1@27241,6030 v1(27231,6030) 27252,6009 27253,6009 RBi_AMP30.1@27253,5982.78
SIPM1_SUMMER1: P1.C1
SIPM1_SUMMER2: P1.C6
SIPM1_SUMMER3: P1.C11
SIPM1_SUMMER4: P1.C16
SIPM1_SUMMER5: P1.C21
SIPM1_SUMMER6: P1.C26
SIPM2_SUMMER1: P1.C2
SIPM2_SUMMER2: P1.C7
SIPM2_SUMMER3: P1.C12
SIPM2_SUMMER4: P1.C17
SIPM2_SUMMER5: P1.C22
SIPM2_SUMMER6: P1.C27
SIPM3_SUMMER1: P1.C3
SIPM3_SUMMER2: P1.C8
SIPM3_SUMMER3: P1.C13
SIPM3_SUMMER4: P1.C18
SIPM3_SUMMER5: P1.C23
SIPM3_SUMMER6: P1.C28
SIPM4_SUMMER1: P1.C4
SIPM4_SUMMER2: P1.C9
SIPM4_SUMMER3: P1.C14
SIPM4_SUMMER4: P1.C19
SIPM4_SUMMER5: P1.C24
SIPM4_SUMMER6: P1.C29
SIPM5_SUMMER1: P1.C5
SIPM5_SUMMER2: P1.C10
SIPM5_SUMMER3: P1.C15
SIPM5_SUMMER4: P1.C20
SIPM5_SUMMER5: P1.C25
SIPM5_SUMMER6: P1.C30
SIPMOUT1_SUMMER1: C5_AMP1.2 | length 574.8
  Top Layer w7: v1(1298,1968) 1332,1934 1332,1910 1359.22,1882.78 C5_AMP1.2@1369,1882.78
  Bottom Layer w7: v1(1298,1968) 1298,1992 1403,2097 1403,2169 1321,2251 1321,2345
SIPMOUT1_SUMMER2: C5_AMP6.2 | length 626.9
  Top Layer w7: C5_AMP6.2@7045.78,6077 7045,6077.78 7045,6170 v1(7061,6186)
  Bottom Layer w7: 7017,6605 7017,6511 7099,6429 7099,6373 7010,6284 7010,6260.31 7061,6209.31 v1(7061,6186)
SIPMOUT1_SUMMER3: C5_AMP11.2 | length 574.8
  Top Layer w7: v1(9245,6199) 9279,6165 9279,6141 9306.22,6113.78 C5_AMP11.2@9316,6113.78
  Bottom Layer w7: v1(9245,6199) 9245,6223 9350,6328 9350,6400 9268,6482 9268,6576
SIPMOUT1_SUMMER4: C5_AMP16.2 | length 574.8
  Top Layer w7: v1(11452,6188) 11486,6154 11486,6130 11513.22,6102.78 C5_AMP16.2@11523,6102.78
  Bottom Layer w7: v1(11452,6188) 11452,6212 11557,6317 11557,6389 11475,6471 11475,6565
SIPMOUT1_SUMMER5: C5_AMP21.2 | length 574.8
  Top Layer w7: v1(13728,6153) 13762,6119 13762,6095 13789.22,6067.78 C5_AMP21.2@13799,6067.78
  Bottom Layer w7: v1(13728,6153) 13728,6177 13833,6282 13833,6354 13751,6436 13751,6530
SIPMOUT1_SUMMER6: C5_AMP26.2 | length 574.8
  Top Layer w7: v1(16656,6143) 16690,6109 16690,6085 16717.22,6057.78 C5_AMP26.2@16727,6057.78
  Bottom Layer w7: v1(16656,6143) 16656,6167 16761,6272 16761,6344 16679,6426 16679,6520
SIPMOUT2_SUMMER1: C5_AMP2.2 | length 574.8
  Top Layer w7: v1(1481,1968) 1515,1934 1515,1910 1542.22,1882.78 C5_AMP2.2@1552,1882.78
  Bottom Layer w7: v1(1481,1968) 1481,1992 1586,2097 1586,2169 1504,2251 1504,2345
SIPMOUT2_SUMMER2: C5_AMP7.2 | length 574.8
  Top Layer w7: v1(7456,6223) 7490,6189 7490,6165 7517.22,6137.78 C5_AMP7.2@7527,6137.78
  Bottom Layer w7: v1(7456,6223) 7456,6247 7561,6352 7561,6424 7479,6506 7479,6600
SIPMOUT2_SUMMER3: C5_AMP12.2 | length 574.8
  Top Layer w7: v1(9809,6221) 9843,6187 9843,6163 9870.22,6135.78 C5_AMP12.2@9880,6135.78
  Bottom Layer w7: v1(9809,6221) 9809,6245 9914,6350 9914,6422 9832,6504 9832,6598
SIPMOUT2_SUMMER4: C5_AMP17.2 | length 574.8
  Top Layer w7: v1(11840,6200) 11874,6166 11874,6142 11901.22,6114.78 C5_AMP17.2@11911,6114.78
  Bottom Layer w7: v1(11840,6200) 11840,6224 11945,6329 11945,6401 11863,6483 11863,6577
SIPMOUT2_SUMMER5: C5_AMP22.2 | length 574.8
  Top Layer w7: v1(14433,6095) 14467,6061 14467,6037 14494.22,6009.78 C5_AMP22.2@14504,6009.78
  Bottom Layer w7: v1(14433,6095) 14433,6119 14538,6224 14538,6296 14456,6378 14456,6472
SIPMOUT2_SUMMER6: C5_AMP27.2 | length 574.8
  Top Layer w7: v1(17186,6154) 17220,6120 17220,6096 17247.22,6068.78 C5_AMP27.2@17257,6068.78
  Bottom Layer w7: v1(17186,6154) 17186,6178 17291,6283 17291,6355 17209,6437 17209,6531
SIPMOUT3_SUMMER1: C5_AMP3.2 | length 574.8
  Top Layer w7: v1(1664,1968) 1698,1934 1698,1910 1725.22,1882.78 C5_AMP3.2@1735,1882.78
  Bottom Layer w7: v1(1664,1968) 1664,1992 1769,2097 1769,2169 1687,2251 1687,2345
SIPMOUT3_SUMMER2: C5_AMP8.2 | length 574.8
  Top Layer w7: v1(7953,6247) 7987,6213 7987,6189 8014.22,6161.78 C5_AMP8.2@8024,6161.78
  Bottom Layer w7: v1(7953,6247) 7953,6271 8058,6376 8058,6448 7976,6530 7976,6624
SIPMOUT3_SUMMER3: C5_AMP13.2 | length 574.8
  Top Layer w7: v1(10196,6199) 10230,6165 10230,6141 10257.22,6113.78 C5_AMP13.2@10267,6113.78
  Bottom Layer w7: v1(10196,6199) 10196,6223 10301,6328 10301,6400 10219,6482 10219,6576
SIPMOUT3_SUMMER4: C5_AMP18.2 | length 574.8
  Top Layer w7: v1(12296,5998) 12330,5964 12330,5940 12357.22,5912.78 C5_AMP18.2@12367,5912.78
  Bottom Layer w7: v1(12296,5998) 12296,6022 12401,6127 12401,6199 12319,6281 12319,6375
SIPMOUT3_SUMMER5: C5_AMP23.2 | length 574.8
  Top Layer w7: v1(15242,6153) 15276,6119 15276,6095 15303.22,6067.78 C5_AMP23.2@15313,6067.78
  Bottom Layer w7: v1(15242,6153) 15242,6177 15347,6282 15347,6354 15265,6436 15265,6530
SIPMOUT3_SUMMER6: C5_AMP28.2 | length 574.8
  Top Layer w7: v1(17717,6154) 17751,6120 17751,6096 17778.22,6068.78 C5_AMP28.2@17788,6068.78
  Bottom Layer w7: v1(17717,6154) 17717,6178 17822,6283 17822,6355 17740,6437 17740,6531
SIPMOUT4_SUMMER1: C5_AMP4.2 | length 574.8
  Top Layer w7: v1(1848,1968) 1882,1934 1882,1910 1909.22,1882.78 C5_AMP4.2@1919,1882.78
  Bottom Layer w7: v1(1848,1968) 1848,1992 1953,2097 1953,2169 1871,2251 1871,2345
SIPMOUT4_SUMMER2: C5_AMP9.2 | length 574.8
  Top Layer w7: v1(8404,6240) 8438,6206 8438,6182 8465.22,6154.78 C5_AMP9.2@8475,6154.78
  Bottom Layer w7: v1(8404,6240) 8404,6264 8509,6369 8509,6441 8427,6523 8427,6617
SIPMOUT4_SUMMER3: C5_AMP14.2 | length 574.8
  Top Layer w7: v1(10562,6199) 10596,6165 10596,6141 10623.22,6113.78 C5_AMP14.2@10633,6113.78
  Bottom Layer w7: v1(10562,6199) 10562,6223 10667,6328 10667,6400 10585,6482 10585,6576
SIPMOUT4_SUMMER4: C5_AMP19.2 | length 574.8
  Top Layer w7: v1(12688,6194) 12722,6160 12722,6136 12749.22,6108.78 C5_AMP19.2@12759,6108.78
  Bottom Layer w7: v1(12688,6194) 12688,6218 12793,6323 12793,6395 12711,6477 12711,6571
SIPMOUT4_SUMMER5: C5_AMP24.2 | length 574.8
  Top Layer w7: v1(15700,6195) 15734,6161 15734,6137 15761.22,6109.78 C5_AMP24.2@15771,6109.78
  Bottom Layer w7: v1(15700,6195) 15700,6219 15805,6324 15805,6396 15723,6478 15723,6572
SIPMOUT4_SUMMER6: C5_AMP29.2 | length 574.8
  Top Layer w7: v1(18134,6195) 18168,6161 18168,6137 18195.22,6109.78 C5_AMP29.2@18205,6109.78
  Bottom Layer w7: v1(18134,6195) 18134,6219 18239,6324 18239,6396 18157,6478 18157,6572
SIPMOUT5_SUMMER1: C5_AMP5.2 | length 574.8
  Top Layer w7: v1(2031,1968) 2065,1934 2065,1910 2092.22,1882.78 C5_AMP5.2@2102,1882.78
  Bottom Layer w7: v1(2031,1968) 2031,1992 2136,2097 2136,2169 2054,2251 2054,2345
SIPMOUT5_SUMMER2: C5_AMP10.2 | length 574.8
  Top Layer w7: v1(8833,6223) 8867,6189 8867,6165 8894.22,6137.78 C5_AMP10.2@8904,6137.78
  Bottom Layer w7: v1(8833,6223) 8833,6247 8938,6352 8938,6424 8856,6506 8856,6600
SIPMOUT5_SUMMER3: C5_AMP15.2 | length 574.8
  Top Layer w7: v1(11030,6156) 11064,6122 11064,6098 11091.22,6070.78 C5_AMP15.2@11101,6070.78
  Bottom Layer w7: v1(11030,6156) 11030,6180 11135,6285 11135,6357 11053,6439 11053,6533
SIPMOUT5_SUMMER4: C5_AMP20.2 | length 574.8
  Top Layer w7: v1(13178,6047) 13212,6013 13212,5989 13239.22,5961.78 C5_AMP20.2@13249,5961.78
  Bottom Layer w7: v1(13178,6047) 13178,6071 13283,6176 13283,6248 13201,6330 13201,6424
SIPMOUT5_SUMMER5: C5_AMP25.2 | length 574.8
  Top Layer w7: v1(16199,6174) 16233,6140 16233,6116 16260.22,6088.78 C5_AMP25.2@16270,6088.78
  Bottom Layer w7: v1(16199,6174) 16199,6198 16304,6303 16304,6375 16222,6457 16222,6551
SIPMOUT5_SUMMER6: C5_AMP30.2 | length 574.8
  Top Layer w7: v1(27252,6327) 27286,6293 27286,6269 27313.22,6241.78 C5_AMP30.2@27323,6241.78
  Bottom Layer w7: v1(27252,6327) 27252,6351 27357,6456 27357,6528 27275,6610 27275,6704
SUMMEDOUT_SUMMER1: P1.A5
SUMMEDOUT_SUMMER1: C9_SUMMER1.2
SUMMEDOUT_SUMMER2: P1.A8
SUMMEDOUT_SUMMER2: C9_SUMMER2.2
SUMMEDOUT_SUMMER3: P1.A13
SUMMEDOUT_SUMMER3: C9_SUMMER3.2
SUMMEDOUT_SUMMER4: P1.A19
SUMMEDOUT_SUMMER4: C9_SUMMER4.2
SUMMEDOUT_SUMMER5: P1.A24
SUMMEDOUT_SUMMER5: C9_SUMMER5.2
SUMMEDOUT_SUMMER6: P1.A32
SUMMEDOUT_SUMMER6: C9_SUMMER6.2
SUMMER1-AMP1-BIAS: P1.B1
TOSUM_SUMMER1: C7_SUMMER1.1 Q3_AMP1.3 Q3_AMP2.3 Q3_AMP3.3 Q3_AMP4.3 Q3_AMP5.3 R9_SUMMER1.2 | length 2579.6
  Top Layer w7: 1275.57,2073.59 1275.57,2102.57 v1(1303,2130) v1@1313.57,2119.43 ; v1@1303,2419 v1(2034,2419) ; 1458.57,2073.59 1458.57,2102.57 v1(1486,2130) v1@1496.57,2119.43 ; 1641.57,2073.59 1641.57,2102.57 v1(1669,2130) v1@1679.57,2119.43 ; 1825.57,2073.59 1825.57,2102.57 v1(1853,2130) v1@1863.57,2119.43 ; 2008.57,2073.59 2008.57,2102.57 v1(2036,2130) v1@2046.57,2119.43
  Bottom Layer w7: v1(1303,2130) v1@1303,2419 ; v1(1486,2130) v1@1486,2416 ; v1(1669,2130) v1@1669,2418 ; v1(1853,2130) v1@1853,2415 ; v1(2036,2130) v1@2036,2417
  other v1: 1484,2419 1669,2419 1849,2419 1301,2421
TOSUM_SUMMER2: C7_SUMMER2.1 Q3_AMP6.3 Q3_AMP7.3 Q3_AMP8.3 Q3_AMP9.3 Q3_AMP10.3 R9_SUMMER2.2 | length 67.7
  Top Layer w7: v1(7000,6379) 7010,6369 Q3_AMP6.3@7010,6315.43
TOSUM_SUMMER3: C7_SUMMER3.1 Q3_AMP11.3 Q3_AMP12.3 Q3_AMP13.3 Q3_AMP14.3 Q3_AMP15.3 R9_SUMMER3.2
TOSUM_SUMMER4: C7_SUMMER4.1 Q3_AMP16.3 Q3_AMP17.3 Q3_AMP18.3 Q3_AMP19.3 Q3_AMP20.3 R9_SUMMER4.2
TOSUM_SUMMER5: C7_SUMMER5.1 Q3_AMP21.3 Q3_AMP22.3 Q3_AMP23.3 Q3_AMP24.3 Q3_AMP25.3 R9_SUMMER5.2
TOSUM_SUMMER6: C7_SUMMER6.1 Q3_AMP26.3 Q3_AMP27.3 Q3_AMP28.3 Q3_AMP29.3 Q3_AMP30.3 R9_SUMMER6.2
VCC: Q8_SUMMER1.3 Q8_SUMMER2.3 Q8_SUMMER3.3 Q8_SUMMER4.3 Q8_SUMMER5.3 Q8_SUMMER6.3 R4_AMP1.2 R4_AMP2.2 R4_AMP3.2 R4_AMP4.2 R4_AMP5.2 R4_AMP6.2 R4_AMP7.2 R4_AMP8.2 R4_AMP9.2 R4_AMP10.2 R4_AMP11.2 R4_AMP12.2 R4_AMP13.2 R4_AMP14.2 R4_AMP15.2 R4_AMP16.2 R4_AMP17.2 R4_AMP18.2 R4_AMP19.2 R4_AMP20.2 R4_AMP21.2 R4_AMP22.2 R4_AMP23.2 R4_AMP24.2 R4_AMP25.2 R4_AMP26.2 R4_AMP27.2 R4_AMP28.2 R4_AMP29.2 R4_AMP30.2 R5_AMP1.2 R5_AMP2.2 R5_AMP3.2 R5_AMP4.2 R5_AMP5.2 R5_AMP6.2 R5_AMP7.2 R5_AMP8.2 R5_AMP9.2 R5_AMP10.2 R5_AMP11.2 R5_AMP12.2 R5_AMP13.2 R5_AMP14.2 R5_AMP15.2 R5_AMP16.2 R5_AMP17.2 R5_AMP18.2 R5_AMP19.2 R5_AMP20.2 R5_AMP21.2 R5_AMP22.2 R5_AMP23.2 R5_AMP24.2 R5_AMP25.2 R5_AMP26.2 R5_AMP27.2 R5_AMP28.2 R5_AMP29.2 R5_AMP30.2 R7_AMP1.2 R7_AMP2.2 R7_AMP3.2 R7_AMP4.2 R7_AMP5.2 R7_AMP6.2 R7_AMP7.2 R7_AMP8.2 R7_AMP9.2 R7_AMP10.2 R7_AMP11.2 R7_AMP12.2 R7_AMP13.2 R7_AMP14.2 R7_AMP15.2 R7_AMP16.2 R7_AMP17.2 R7_AMP18.2 R7_AMP19.2 R7_AMP20.2 R7_AMP21.2 R7_AMP22.2 R7_AMP23.2 R7_AMP24.2 R7_AMP25.2 R7_AMP26.2 R7_AMP27.2 R7_AMP28.2 R7_AMP29.2 R7_AMP30.2 R8_AMP1.2 R8_AMP2.2 R8_AMP3.2 R8_AMP4.2 R8_AMP5.2 R8_AMP6.2 R8_AMP7.2 R8_AMP8.2 R8_AMP9.2 R8_AMP10.2 R8_AMP11.2 R8_AMP12.2 R8_AMP13.2 R8_AMP14.2 R8_AMP15.2 R8_AMP16.2 R8_AMP17.2 R8_AMP18.2 R8_AMP19.2 R8_AMP20.2 R8_AMP21.2 R8_AMP22.2 R8_AMP23.2 R8_AMP24.2 R8_AMP25.2 R8_AMP26.2 R8_AMP27.2 R8_AMP28.2 R8_AMP29.2 R8_AMP30.2 R10_SUMMER1.2 R10_SUMMER2.2 R10_SUMMER3.2 R10_SUMMER4.2 R10_SUMMER5.2 R10_SUMMER6.2 R11_SUMMER1.2 R11_SUMMER2.2 R11_SUMMER3.2 R11_SUMMER4.2 R11_SUMMER5.2 R11_SUMMER6.2 R13_SUMMER1.2 R13_SUMMER2.2 R13_SUMMER3.2 R13_SUMMER4.2 R13_SUMMER5.2 R13_SUMMER6.2 R15_SUMMER1.2 R15_SUMMER2.2 R15_SUMMER3.2 R15_SUMMER4.2 R15_SUMMER5.2 R15_SUMMER6.2 R16_SUMMER1.2 R16_SUMMER2.2 R16_SUMMER3.2 R16_SUMMER4.2 R16_SUMMER5.2 R16_SUMMER6.2 R20_AMP1.2 R20_AMP2.2 R20_AMP3.2 R20_AMP4.2 R20_AMP5.2 R20_AMP6.2 R20_AMP7.2 R20_AMP8.2 R20_AMP9.2 R20_AMP10.2 R20_AMP11.2 R20_AMP12.2 R20_AMP13.2 R20_AMP14.2 R20_AMP15.2 R20_AMP16.2 R20_AMP17.2 R20_AMP18.2 R20_AMP19.2 R20_AMP20.2 R20_AMP21.2 R20_AMP22.2 R20_AMP23.2 R20_AMP24.2 R20_AMP25.2 R20_AMP26.2 R20_AMP27.2 R20_AMP28.2 R20_AMP29.2 R20_AMP30.2 RD_SUMMER1.2 RD_SUMMER2.2 RD_SUMMER3.2 RD_SUMMER4.2 RD_SUMMER5.2 RD_SUMMER6.2 | length 6850.3
  Top Layer w7: R16_SUMMER1.2@1285,2598.78 v1(1285,2644) 1296,2655 R15_SUMMER1.2@1331.22,2655 ; R4_AMP1.2@1342.78,1729 v1@1382,1729 ; v1@1348,1963 v1@1348.22,1962.78 ; R5_AMP1.2@1349.78,1765.22 v1(1384,1731) ; v1(1358,1968) 1369.22,1956.78 R8_AMP1.2@1369.22,1919 ; R20_AMP1.2@1389,1692.78 v1@1389,1726 ; v1@1389,1736 R7_AMP1.2@1389,1775.22 ; RD_SUMMER1.2@1524,2750.78 1529.78,2756.56 1549.67,2756.56 1559.1,2766 v1(1606,2766) ; R4_AMP2.2@1525.78,1729 v1@1565,1729 ; v1@1531,1963 v1@1531.22,1962.78 ; R5_AMP2.2@1532.78,1765.22 v1(1567,1731) ; v1(1541,1968) 1552.22,1956.78 R8_AMP2.2@1552.22,1919 ; R20_AMP2.2@1572,1692.78 v1@1572,1726 ; v1@1572,1736 R7_AMP2.2@1572,1775.22 ; R4_AMP3.2@1708.78,1729 v1@1748,1729 ; v1@1714,1963 v1@1714.22,1962.78 ; R5_AMP3.2@1715.78,1765.22 v1(1750,1731) ; v1(1724,1968) 1735.22,1956.78 R8_AMP3.2@1735.22,1919 ; R20_AMP3.2@1755,1692.78 v1@1755,1726 ; v1@1755,1736 R7_AMP3.2@1755,1775.22 ; v1@1760,2565 R11_SUMMER1.2@1760,2518.78 1778.01,2518.78 1789.23,2530 Q8_SUMMER1.3@1823.66,2530 ; R4_AMP4.2@1892.78,1729 v1@1932,1729 ; v1@1898,1963 v1@1898.22,1962.78 ; R5_AMP4.2@1899.78,1765.22 v1(1934,1731) ; v1(1908,1968) 1919.22,1956.78 R8_AMP4.2@1919.22,1919 ; R20_AMP4.2@1939,1692.78 v1@1939,1726 ; v1@1939,1736 R7_AMP4.2@1939,1775.22 ; v1@2035,2557 R10_SUMMER1.2@2035,2611.22 ; R4_AMP5.2@2075.78,1729 v1@2115,1729 ; v1@2081,1963 v1@2081.22,1962.78 ; R5_AMP5.2@2082.78,1765.22 v1(2117,1731) ; v1(2091,1968) 2102.22,1956.78 R8_AMP5.2@2102.22,1919 ; R20_AMP5.2@2122,1692.78 v1@2122,1726 ; v1@2122,1736 R7_AMP5.2@2122,1775.22 ; R20_AMP6.2@7057.44,5915 7057.44,5927.44 v1(7089,5959) ; R4_AMP6.2@7059.37,5993.59 R4_AMP6.2@7053.78,5988 7060,5988 v1(7089,5959) ; R8_AMP6.2@7065,6110.6 7074.84,6100.76 7074.84,6051 7077.4,6048.44 R5_AMP6.2@7077.4,6013 ; 7077.4,6044.22 R7_AMP6.2@7095,6044.22 ; R5_AMP6.2@7078.78,6013 7089,6002.78 v1(7089,5959) ; R4_AMP7.2@7500.78,5984 v1@7540,5984 ; v1@7506,6218 v1@7506.22,6217.78 ; R5_AMP7.2@7507.78,6020.22 v1(7542,5986) ; v1(7516,6223) 7527.22,6211.78 R8_AMP7.2@7527.22,6174 ; R20_AMP7.2@7547,5947.78 v1@7547,5981 ; v1@7547,5991 R7_AMP7.2@7547,6030.22 ; R4_AMP8.2@7997.78,6008 v1@8037,6008 ; v1@8003,6242 v1@8003.22,6241.78 ; R5_AMP8.2@8004.78,6044.22 v1(8039,6010) ; v1(8013,6247) 8024.22,6235.78 R8_AMP8.2@8024.22,6198 ; R20_AMP8.2@8044,5971.78 v1@8044,6005 ; v1@8044,6015 R7_AMP8.2@8044,6054.22 ; R4_AMP9.2@8448.78,6001 v1@8488,6001 ; v1@8454,6235 v1@8454.22,6234.78 ; R5_AMP9.2@8455.78,6037.22 v1(8490,6003) ; v1(8464,6240) 8475.22,6228.78 R8_AMP9.2@8475.22,6191 ; R20_AMP9.2@8495,5964.78 v1@8495,5998 ; v1@8495,6008 R7_AMP9.2@8495,6047.22 ; R4_AMP10.2@8877.78,5984 v1@8917,5984 ; v1@8883,6218 v1@8883.22,6217.78 ; R5_AMP10.2@8884.78,6020.22 v1(8919,5986) ; v1(8893,6223) 8904.22,6211.78 R8_AMP10.2@8904.22,6174 ; R20_AMP10.2@8924,5947.78 v1@8924,5981 ; v1@8924,5991 R7_AMP10.2@8924,6030.22 ; R4_AMP11.2@9289.78,5960 v1@9329,5960 ; v1@9295,6194 v1@9295.22,6193.78 ; R5_AMP11.2@9296.78,5996.22 v1(9331,5962) ; v1(9305,6199) 9316.22,6187.78 R8_AMP11.2@9316.22,6150 ; R20_AMP11.2@9336,5923.78 v1@9336,5957 ; v1@9336,5967 R7_AMP11.2@9336,6006.22 ; R4_AMP12.2@9853.78,5982 v1@9893,5982 ; v1@9859,6216 v1@9859.22,6215.78 ; R5_AMP12.2@9860.78,6018.22 v1(9895,5984) ; v1(9869,6221) 9880.22,6209.78 R8_AMP12.2@9880.22,6172 ; R20_AMP12.2@9900,5945.78 v1@9900,5979 ; v1@9900,5989 R7_AMP12.2@9900,6028.22 ; R4_AMP13.2@10240.78,5960 v1@10280,5960 ; v1@10246,6194 v1@10246.22,6193.78 ; R5_AMP13.2@10247.78,5996.22 v1(10282,5962) ; v1(10256,6199) 10267.22,6187.78 R8_AMP13.2@10267.22,6150 ; R20_AMP13.2@10287,5923.78 v1@10287,5957 ; v1@10287,5967 R7_AMP13.2@10287,6006.22 ; R4_AMP14.2@10606.78,5960 v1@10646,5960 ; v1@10612,6194 v1@10612.22,6193.78 ; R5_AMP14.2@10613.78,5996.22 v1(10648,5962) ; v1(10622,6199) 10633.22,6187.78 R8_AMP14.2@10633.22,6150 ; R20_AMP14.2@10653,5923.78 v1@10653,5957 ; v1@10653,5967 R7_AMP14.2@10653,6006.22 ; R4_AMP15.2@11074.78,5917 v1@11114,5917 ; v1@11080,6151 v1@11080.22,6150.78 ; R5_AMP15.2@11081.78,5953.22 v1(11116,5919) ; v1(11090,6156) 11101.22,6144.78 R8_AMP15.2@11101.22,6107 ; R20_AMP15.2@11121,5880.78 v1@11121,5914 ; v1@11121,5924 R7_AMP15.2@11121,5963.22 ; R4_AMP16.2@11496.78,5949 v1@11536,5949 ; v1@11502,6183 v1@11502.22,6182.78 ; R5_AMP16.2@11503.78,5985.22 v1(11538,5951) ; v1(11512,6188) 11523.22,6176.78 R8_AMP16.2@11523.22,6139 ; R20_AMP16.2@11543,5912.78 v1@11543,5946 ; v1@11543,5956 R7_AMP16.2@11543,5995.22 ; R4_AMP17.2@11884.78,5961 v1@11924,5961 ; v1@11890,6195 v1@11890.22,6194.78 ; R5_AMP17.2@11891.78,5997.22 v1(11926,5963) ; v1(11900,6200) 11911.22,6188.78 R8_AMP17.2@11911.22,6151 ; R20_AMP17.2@11931,5924.78 v1@11931,5958 ; v1@11931,5968 R7_AMP17.2@11931,6007.22 ; R4_AMP18.2@12340.78,5759 v1@12380,5759 ; v1@12346,5993 v1@12346.22,5992.78 ; R5_AMP18.2@12347.78,5795.22 v1(12382,5761) ; v1(12356,5998) 12367.22,5986.78 R8_AMP18.2@12367.22,5949 ; R20_AMP18.2@12387,5722.78 v1@12387,5756 ; v1@12387,5766 R7_AMP18.2@12387,5805.22 ; R4_AMP19.2@12732.78,5955 v1@12772,5955 ; v1@12738,6189 v1@12738.22,6188.78 ; R5_AMP19.2@12739.78,5991.22 v1(12774,5957) ; v1(12748,6194) 12759.22,6182.78 R8_AMP19.2@12759.22,6145 ; R20_AMP19.2@12779,5918.78 v1@12779,5952 ; v1@12779,5962 R7_AMP19.2@12779,6001.22 ; R4_AMP20.2@13222.78,5808 v1@13262,5808 ; v1@13228,6042 v1@13228.22,6041.78 ; R5_AMP20.2@13229.78,5844.22 v1(13264,5810) ; v1(13238,6047) 13249.22,6035.78 R8_AMP20.2@13249.22,5998 ; R20_AMP20.2@13269,5771.78 v1@13269,5805 ; v1@13269,5815 R7_AMP20.2@13269,5854.22 ; R4_AMP21.2@13772.78,5914 v1@13812,5914 ; v1@13778,6148 v1@13778.22,6147.78 ; R5_AMP21.2@13779.78,5950.22 v1(13814,5916) ; v1(13788,6153) 13799.22,6141.78 R8_AMP21.2@13799.22,6104 ; R20_AMP21.2@13819,5877.78 v1@13819,5911 ; v1@13819,5921 R7_AMP21.2@13819,5960.22 ; R4_AMP22.2@14477.78,5856 v1@14517,5856 ; v1@14483,6090 v1@14483.22,6089.78 ; R5_AMP22.2@14484.78,5892.22 v1(14519,5858) ; v1(14493,6095) 14504.22,6083.78 R8_AMP22.2@14504.22,6046 ; R20_AMP22.2@14524,5819.78 v1@14524,5853 ; v1@14524,5863 R7_AMP22.2@14524,5902.22 ; R4_AMP23.2@15286.78,5914 v1@15326,5914 ; v1@15292,6148 v1@15292.22,6147.78 ; R5_AMP23.2@15293.78,5950.22 v1(15328,5916) ; v1(15302,6153) 15313.22,6141.78 R8_AMP23.2@15313.22,6104 ; R20_AMP23.2@15333,5877.78 v1@15333,5911 ; v1@15333,5921 R7_AMP23.2@15333,5960.22 ; R4_AMP24.2@15744.78,5956 v1@15784,5956 ; v1@15750,6190 v1@15750.22,6189.78 ; R5_AMP24.2@15751.78,5992.22 v1(15786,5958) ; v1(15760,6195) 15771.22,6183.78 R8_AMP24.2@15771.22,6146 ; R20_AMP24.2@15791,5919.78 v1@15791,5953 ; v1@15791,5963 R7_AMP24.2@15791,6002.22 ; R4_AMP25.2@16243.78,5935 v1@16283,5935 ; v1@16249,6169 v1@16249.22,6168.78 ; R5_AMP25.2@16250.78,5971.22 v1(16285,5937) ; v1(16259,6174) 16270.22,6162.78 R8_AMP25.2@16270.22,6125 ; R20_AMP25.2@16290,5898.78 v1@16290,5932 ; v1@16290,5942 R7_AMP25.2@16290,5981.22 ; R4_AMP26.2@16700.78,5904 v1@16740,5904 ; v1@16706,6138 v1@16706.22,6137.78 ; R5_AMP26.2@16707.78,5940.22 v1(16742,5906) ; v1(16716,6143) 16727.22,6131.78 R8_AMP26.2@16727.22,6094 ; R20_AMP26.2@16747,5867.78 v1@16747,5901 ; v1@16747,5911 R7_AMP26.2@16747,5950.22 ; R4_AMP27.2@17230.78,5915 v1@17270,5915 ; v1@17236,6149 v1@17236.22,6148.78 ; R5_AMP27.2@17237.78,5951.22 v1(17272,5917) ; v1(17246,6154) 17257.22,6142.78 R8_AMP27.2@17257.22,6105 ; R20_AMP27.2@17277,5878.78 v1@17277,5912 ; v1@17277,5922 R7_AMP27.2@17277,5961.22 ; R4_AMP28.2@17761.78,5915 v1@17801,5915 ; v1@17767,6149 v1@17767.22,6148.78 ; R5_AMP28.2@17768.78,5951.22 v1(17803,5917) ; v1(17777,6154) 17788.22,6142.78 R8_AMP28.2@17788.22,6105 ; R20_AMP28.2@17808,5878.78 v1@17808,5912 ; v1@17808,5922 R7_AMP28.2@17808,5961.22 ; R4_AMP29.2@18178.78,5956 v1@18218,5956 ; v1@18184,6190 v1@18184.22,6189.78 ; R5_AMP29.2@18185.78,5992.22 v1(18220,5958) ; v1(18194,6195) 18205.22,6183.78 R8_AMP29.2@18205.22,6146 ; R20_AMP29.2@18225,5919.78 v1@18225,5953 ; v1@18225,5963 R7_AMP29.2@18225,6002.22 ; R4_AMP30.2@27296.78,6088 v1@27336,6088 ; v1@27302,6322 v1@27302.22,6321.78 ; R5_AMP30.2@27303.78,6124.22 v1(27338,6090) ; v1(27312,6327) 27323.22,6315.78 R8_AMP30.2@27323.22,6278 ; R20_AMP30.2@27343,6051.78 v1@27343,6085 ; v1@27343,6095 R7_AMP30.2@27343,6134.22
  other v1: 2034,2556 1763,2568
pads on no net: M1_SUMMER1.2 M1_SUMMER2.2 M1_SUMMER3.2 M1_SUMMER4.2 M1_SUMMER5.2 M1_SUMMER6.2 P1.33 P1.34 P1.A1 P1.A2 P1.A3 P1.A4 P1.A6 P1.A7 P1.A9 P1.A10 P1.A11 P1.A12 P1.A14 P1.A15 P1.A16 P1.A17 P1.A18 P1.A20 P1.A21 P1.A22 P1.A23 P1.A25 P1.A26 P1.A27 P1.A28 P1.A29 P1.A30 P1.A31 P1.B2 P1.B3 P1.B4 P1.B5 P1.B6 P1.B7 P1.B8 P1.B9 P1.B10 P1.B11 P1.B12 P1.B13 P1.B14 P1.B15 P1.B16 P1.B17 P1.B18 P1.B19 P1.B20 P1.B21 P1.B22 P1.B23 P1.B24 P1.B25 P1.B26 P1.B27 P1.B28 P1.B29 P1.B30 P1.B32 P1.C31 P1.C32

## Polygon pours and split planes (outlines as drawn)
GND on GND (split plane): 6979.61,1020.39 1020.39,1020.39 1020.39,4979.61 6979.61,4979.61
VCC on VCC (split plane): 6979.61,1020.39 1020.39,1020.39 1020.39,4979.61 6979.61,4979.61
NetR25_2 on InternalPlane3 (split plane): 6979.61,1020.39 1020.39,1020.39 1020.39,4979.61 6979.61,4979.61
NetR26_2 on InternalPlane4 (split plane): 6979.61,1020.39 1020.39,1020.39 1020.39,4979.61 6979.61,4979.61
